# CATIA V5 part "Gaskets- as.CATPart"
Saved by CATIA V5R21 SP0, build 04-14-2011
Part number: Gaskets
Bounding box of the stored display mesh (mm): x -30 to 30, y -30 to 30, z -2 to 9
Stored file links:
  D:\Koje\수업\Catia\자격증 특강\자격시험예제\Pipe-sample3\Gaskets- as.CATPart
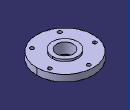
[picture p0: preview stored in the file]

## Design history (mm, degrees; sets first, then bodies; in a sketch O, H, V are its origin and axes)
Body1 (main body)
  Sketch1 on xy-plane, origin (0, 0, 0), H (1, 0, 0), V (0, 1, 0)
    circle A1 centre (0, 0) radius 30
    radius A1 = 30
  Pad1: profile Sketch1, direction (0, 0, 1), length 7
  Sketch2 on end face of Pad1, origin (0, 0, 7), H (1, 0, 0), V (0, 1, 0)
    circle A1 centre (0, 0) radius 13.5
    radius A1 = 13.5
  Pad2: profile Sketch2, direction (0, 0, 1), length 2, opposite side length 9
  Sketch3 on end face of Pad2, origin (-1.5598, 3.076, 9), H (1, 0, 0), V (0, 1, 0)
    point P1 (1.5598, -3.076)
    reference projected circle E1 centre (1.5598, -3.076) radius 13.5 from edge [face of Pad2 from Sketch2.A1 | end face of Pad2]
    concentricity: E1 P1
  Hole1: placed by Sketch3, at (0, 0, 9) direction (0, 0, -1), diameter 18, through (limit type 6)
  Sketch4 on end face of Pad1, origin (0, 0, 7), H (1, 0, 0), V (0, 1, 0)
    point P1 (0, 25)
    distance P1 H = 25
    coincidence: V P1
  Hole2: placed by Sketch4, at (0, 25, 7) direction (0, 0, -1), diameter 4, through (limit type 6)
  CircPattern1: of Hole2, instances 5, angular step 72 {= 360.0*1 deg/CircPattern1.AngularNumber}, axis from Z axis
